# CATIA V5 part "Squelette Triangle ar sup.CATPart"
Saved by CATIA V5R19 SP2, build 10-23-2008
Part number: Squelette Triangle ar sup
Bounding box of the stored display mesh (mm): x 296.217 to 333.217, y -265.605 to -192.195, z 62.133 to 78.541
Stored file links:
  D:\Mes Documents\ressource\CATIA\Ensemble Catia\Voiture_Telecommmande\SchemaCinematiqueFinal\Squelette Triangle ar sup.CATPart
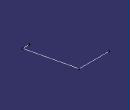
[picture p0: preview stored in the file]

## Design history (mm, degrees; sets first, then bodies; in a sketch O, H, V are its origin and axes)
AxisSystem1: origin (0, 0, 0), X (1, 0, 0), Y (0, 1, 0), Z (0, 0, 1)
Body1 (main body)
  Line1 to Line3: stored without definition
  Point1: stored without definition
  Point2: stored without definition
